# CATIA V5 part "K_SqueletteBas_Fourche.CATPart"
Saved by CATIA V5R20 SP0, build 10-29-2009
Part number: Squelette_Bas_Fourche
Bounding box of the stored display mesh (mm): x -88.355 to 72.073, y -518.505 to -284.244, z -542.828 to -344.888
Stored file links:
  G:\Khaled_CFAO_2011\ST2M\ST2M_GR1\bmartinez\Khaled\CAD_ThinkMOTION\K_SqueletteBas_Fourche.CATPart
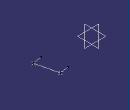
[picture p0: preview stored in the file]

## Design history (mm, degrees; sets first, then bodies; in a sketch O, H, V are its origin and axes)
Set1
  Line1: type PtDir, RefPoint Point1, Direction Plane1, Start 0, End 160
  Point1: stored without definition
  Plane1: stored without definition
  Line2: type Normal, RefPoint Point2, RefSkin Plane2, Start 0, End 160
  Plane2: stored without definition
  Point2: stored without definition
  Point3: type OnCurve, Support Line2, Length 160
  Point4: type OnCurve, Support Line1, Length 160
  Line3: type PtPt, FirstPoint Point4, SecondPoint Point3
Body1 (main body)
